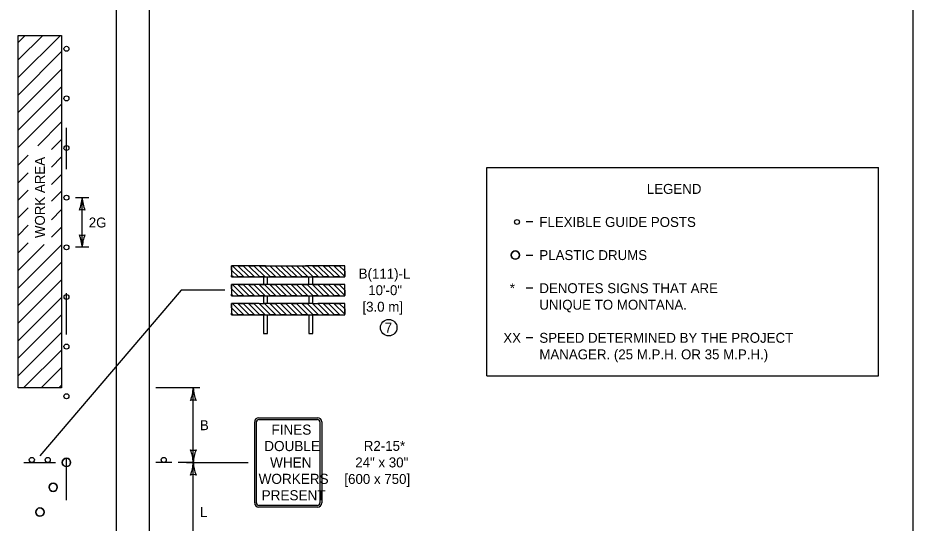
# Model space of a CAD drawing. Extents: x 49991.4 to 50021, y 49987.6 to 50011.4.
# Drawn here: x 50003.21 to 50008.61, y 50003.87 to 50006.92 of the extents above; entities that cross this region are included whole.
import ezdxf

# ---------------------------------------------------------------- set-up
doc = ezdxf.new("R2010")
doc.units = 0
for name, color, linetype in [('Level 1', 7, 'Continuous'), ('Level 2', 7, 'Continuous'), ('Level 3', 7, 'Continuous')]:
    doc.layers.add(name, color=color, linetype=linetype)

msp = doc.modelspace()

# ---------------------------------------------------------------- linework, layer by layer
at = {"layer": 'Level 1'}
for p, q in [((50003.8002, 50009.1708), (50003.8002, 50000.6526)), ((50004.0002, 50009.1708), (50004.0002, 50000.6526)), ((50003.2093, 50006.8139), (50003.4712, 50006.8139)), ((50003.2093, 50004.6829), (50003.2093, 50006.8139)), ((50003.2093, 50006.6656), (50003.3576, 50006.8139)), ((50003.2093, 50006.7716), (50003.2515, 50006.8139)), ((50003.2093, 50006.5595), (50003.4637, 50006.8139)), ((50003.4712, 50006.8139), (50003.4712, 50004.6829)), ((50003.2093, 50006.4534), (50003.4712, 50006.7154)), ((50003.2093, 50006.3474), (50003.4712, 50006.6093)), ((50003.2093, 50006.2413), (50003.4712, 50006.5032)), ((50003.2093, 50006.1352), (50003.4712, 50006.3972)), ((50003.327, 50006.1469), (50003.4712, 50006.2911)), ((50003.5003, 50006.0059), (50003.5003, 50006.2559)), ((50003.4102, 50006.1241), (50003.4712, 50006.185)), ((50003.2093, 50006.0292), (50003.2702, 50006.0901)), ((50003.4102, 50006.018), (50003.4712, 50006.079)), ((50003.2093, 50005.9231), (50003.2702, 50005.9841)), ((50003.4102, 50005.9119), (50003.4712, 50005.9729)), ((50003.2093, 50005.817), (50003.2702, 50005.878)), ((50003.4102, 50005.8119), (50003.4712, 50005.8729)), ((50003.2093, 50005.711), (50003.2702, 50005.7719)), ((50003.4102, 50005.6998), (50003.4712, 50005.7608)), ((50003.2093, 50005.6049), (50003.2702, 50005.6659)), ((50003.4102, 50005.5937), (50003.4712, 50005.6547)), ((50003.2093, 50005.4988), (50003.2702, 50005.5598)), ((50003.2093, 50005.3928), (50003.3665, 50005.55)), ((50003.4102, 50005.4877), (50003.4712, 50005.5486)), ((50003.2093, 50005.2867), (50003.4102, 50005.4877)), ((50003.2093, 50005.1806), (50003.4712, 50005.4426)), ((50004.5397, 50005.3536), (50004.4979, 50005.3954)), ((50004.5397, 50005.3536), (50004.4979, 50005.3954)), ((50004.5719, 50005.3536), (50004.5035, 50005.422)), ((50004.5035, 50005.422), (50004.5719, 50005.3536)), ((50004.6042, 50005.3536), (50004.5358, 50005.422)), ((50004.6042, 50005.3536), (50004.5358, 50005.422)), ((50004.6364, 50005.3536), (50004.568, 50005.422)), ((50004.568, 50005.422), (50004.6364, 50005.3536)), ((50004.6687, 50005.3536), (50004.6003, 50005.422)), ((50004.6687, 50005.3536), (50004.6003, 50005.422)), ((50004.7009, 50005.3536), (50004.6325, 50005.422)), ((50004.6325, 50005.422), (50004.7009, 50005.3536)), ((50004.7332, 50005.3536), (50004.6648, 50005.422)), ((50004.7654, 50005.3536), (50004.697, 50005.422)), ((50004.697, 50005.422), (50004.7369, 50005.422)), ((50004.7174, 50005.422), (50004.9625, 50005.422)), ((50004.7976, 50005.3536), (50004.7292, 50005.422)), ((50004.8298, 50005.3536), (50004.7614, 50005.422)), ((50004.862, 50005.3536), (50004.7936, 50005.422)), ((50004.8942, 50005.3536), (50004.8258, 50005.422)), ((50004.9264, 50005.3536), (50004.858, 50005.422)), ((50004.9586, 50005.3536), (50004.8902, 50005.422)), ((50004.991, 50005.3536), (50004.9226, 50005.422)), ((50004.9767, 50005.422), (50004.9454, 50005.422)), ((50005.0233, 50005.3536), (50004.9549, 50005.422)), ((50005.0556, 50005.3536), (50004.9872, 50005.422)), ((50005.0556, 50005.3536), (50004.9872, 50005.422)), ((50005.0878, 50005.3536), (50005.0194, 50005.422)), ((50005.0194, 50005.422), (50005.0878, 50005.3536)), ((50005.12, 50005.3536), (50005.0516, 50005.422)), ((50005.12, 50005.3536), (50005.0516, 50005.422)), ((50005.1522, 50005.3536), (50005.0838, 50005.422)), ((50005.0838, 50005.422), (50005.1522, 50005.3536)), ((50005.1819, 50005.3562), (50005.1161, 50005.422)), ((50005.1819, 50005.3562), (50005.1161, 50005.422)), ((50005.1819, 50005.3884), (50005.1484, 50005.422)), ((50005.1484, 50005.422), (50005.1819, 50005.3884)), ((50003.2093, 50005.0746), (50003.4712, 50005.3365)), ((50004.5075, 50005.3536), (50004.4979, 50005.3631)), ((50004.4979, 50005.3631), (50004.5075, 50005.3536)), ((50004.7145, 50005.3081), (50004.7145, 50005.3536)), ((50004.9653, 50005.3081), (50004.9653, 50005.3536)), ((50004.5397, 50005.2397), (50004.4979, 50005.2814)), ((50004.5397, 50005.2397), (50004.4979, 50005.2814)), ((50004.5719, 50005.2397), (50004.5035, 50005.3081)), ((50004.5035, 50005.3081), (50004.5719, 50005.2397)), ((50004.6042, 50005.2397), (50004.5358, 50005.3081)), ((50004.6042, 50005.2397), (50004.5358, 50005.3081)), ((50004.6364, 50005.2397), (50004.568, 50005.3081)), ((50004.568, 50005.3081), (50004.6364, 50005.2397)), ((50004.6687, 50005.2397), (50004.6003, 50005.3081)), ((50004.6687, 50005.2397), (50004.6003, 50005.3081)), ((50004.7009, 50005.2397), (50004.6325, 50005.3081)), ((50004.6325, 50005.3081), (50004.7009, 50005.2397)), ((50004.7031, 50005.2697), (50004.6648, 50005.3081)), ((50004.7031, 50005.3019), (50004.697, 50005.3081)), ((50004.7654, 50005.2397), (50004.7031, 50005.3019)), ((50004.7332, 50005.2397), (50004.7031, 50005.2697)), ((50004.7976, 50005.2397), (50004.7292, 50005.3081)), ((50004.8298, 50005.2397), (50004.7614, 50005.3081)), ((50004.8621, 50005.2397), (50004.7937, 50005.3081)), ((50004.8944, 50005.2397), (50004.826, 50005.3081)), ((50004.9266, 50005.2397), (50004.8582, 50005.3081)), ((50004.9588, 50005.2397), (50004.8904, 50005.3081)), ((50004.991, 50005.2397), (50004.9226, 50005.3081)), ((50005.0233, 50005.2397), (50004.9549, 50005.3081)), ((50005.0556, 50005.2397), (50004.9872, 50005.3081)), ((50005.0556, 50005.2397), (50004.9872, 50005.3081)), ((50005.0878, 50005.2397), (50005.0194, 50005.3081)), ((50005.0194, 50005.3081), (50005.0878, 50005.2397)), ((50005.12, 50005.2397), (50005.0516, 50005.3081)), ((50005.12, 50005.2397), (50005.0516, 50005.3081)), ((50005.1522, 50005.2397), (50005.0838, 50005.3081)), ((50005.0838, 50005.3081), (50005.1522, 50005.2397)), ((50005.1819, 50005.2422), (50005.1161, 50005.3081)), ((50005.1819, 50005.2422), (50005.1161, 50005.3081)), ((50005.1819, 50005.2744), (50005.1484, 50005.3081)), ((50005.1484, 50005.3081), (50005.1819, 50005.2744)), ((50003.2093, 50004.9685), (50003.4712, 50005.2304)), ((50003.5003, 50005.0059), (50003.5003, 50005.2559)), ((50004.5075, 50005.2397), (50004.4979, 50005.2492)), ((50004.4979, 50005.2492), (50004.5075, 50005.2397)), ((50004.5397, 50005.1257), (50004.4979, 50005.1674)), ((50004.5397, 50005.1257), (50004.4979, 50005.1674)), ((50004.5719, 50005.1257), (50004.5035, 50005.1941)), ((50004.5035, 50005.1941), (50004.5719, 50005.1257)), ((50004.6042, 50005.1257), (50004.5358, 50005.1941)), ((50004.6042, 50005.1257), (50004.5358, 50005.1941)), ((50004.6364, 50005.1257), (50004.568, 50005.1941)), ((50004.568, 50005.1941), (50004.6364, 50005.1257)), ((50004.6687, 50005.1257), (50004.6003, 50005.1941)), ((50004.6687, 50005.1257), (50004.6003, 50005.1941)), ((50004.7009, 50005.1257), (50004.6325, 50005.1941)), ((50004.6325, 50005.1941), (50004.7009, 50005.1257)), ((50004.7332, 50005.1257), (50004.6648, 50005.1941)), ((50004.7332, 50005.1257), (50004.6648, 50005.1941)), ((50004.7654, 50005.1257), (50004.697, 50005.1941)), ((50004.697, 50005.1941), (50004.7654, 50005.1257)), ((50004.7976, 50005.1257), (50004.7292, 50005.1941)), ((50004.7976, 50005.1257), (50004.7292, 50005.1941)), ((50004.8298, 50005.1257), (50004.7614, 50005.1941)), ((50004.7614, 50005.1941), (50004.8298, 50005.1257)), ((50004.8621, 50005.1257), (50004.7937, 50005.1941)), ((50004.8621, 50005.1257), (50004.7937, 50005.1941)), ((50004.8944, 50005.1257), (50004.826, 50005.1941)), ((50004.826, 50005.1941), (50004.8944, 50005.1257)), ((50004.9266, 50005.1257), (50004.8582, 50005.1941)), ((50004.9266, 50005.1257), (50004.8582, 50005.1941)), ((50004.9588, 50005.1257), (50004.8904, 50005.1941)), ((50004.8904, 50005.1941), (50004.9588, 50005.1257)), ((50004.991, 50005.1257), (50004.9226, 50005.1941)), ((50004.991, 50005.1257), (50004.9226, 50005.1941)), ((50005.0233, 50005.1257), (50004.9549, 50005.1941)), ((50004.9549, 50005.1941), (50005.0233, 50005.1257)), ((50005.0556, 50005.1257), (50004.9872, 50005.1941)), ((50005.0556, 50005.1257), (50004.9872, 50005.1941)), ((50005.0878, 50005.1257), (50005.0194, 50005.1941)), ((50005.0194, 50005.1941), (50005.0878, 50005.1257)), ((50005.12, 50005.1257), (50005.0516, 50005.1941)), ((50005.12, 50005.1257), (50005.0516, 50005.1941)), ((50005.1522, 50005.1257), (50005.0838, 50005.1941)), ((50005.0838, 50005.1941), (50005.1522, 50005.1257)), ((50005.1819, 50005.1282), (50005.1161, 50005.1941)), ((50005.1819, 50005.1282), (50005.1161, 50005.1941)), ((50005.1819, 50005.1605), (50005.1484, 50005.1941)), ((50005.1484, 50005.1941), (50005.1819, 50005.1605)), ((50003.2093, 50004.8624), (50003.4712, 50005.1244)), ((50004.5075, 50005.1257), (50004.4979, 50005.1352)), ((50004.4979, 50005.1352), (50004.5075, 50005.1257)), ((50003.2093, 50004.7564), (50003.4712, 50005.0183)), ((50003.2419, 50004.6829), (50003.4712, 50004.9122)), ((50003.3479, 50004.6829), (50003.4712, 50004.8062)), ((50003.4712, 50004.6829), (50003.2093, 50004.6829)), ((50003.454, 50004.6829), (50003.4712, 50004.7001)), ((50004.6374, 50003.9882), (50004.6374, 50004.4776)), ((50004.6479, 50003.9882), (50004.6479, 50004.4776)), ((50004.6627, 50004.503), (50005.0171, 50004.503)), ((50004.6627, 50004.4924), (50005.0171, 50004.4924)), ((50004.8399, 50004.503), (50004.8399, 50004.503)), ((50005.0319, 50004.4776), (50005.0319, 50003.9882)), ((50005.0424, 50004.4776), (50005.0424, 50003.9882)), ((50003.5003, 50004.0059), (50003.5003, 50004.2559)), ((50003.2433, 50004.2329), (50003.3393, 50004.2329)), ((50003.3393, 50004.2329), (50003.4353, 50004.2329)), ((50004.1362, 50004.2329), (50004.0402, 50004.2329)), ((50005.0171, 50003.9734), (50004.6627, 50003.9734)), ((50005.0171, 50003.9629), (50004.6627, 50003.9629))]:
    msp.add_line(p, q, dxfattribs=at)
msp.add_lwpolyline([(50008.6146, 50011.2628), (50000.3356, 50011.2628), (50000.3356, 50000.0624), (50008.6146, 50000.0624)], close=True, dxfattribs=at)
for points in [[(50004.7031, 50005.422), (50004.4979, 50005.422), (50004.4979, 50005.3536), (50004.7031, 50005.3536)], [(50004.4979, 50005.3954), (50004.4979, 50005.422), (50004.5035, 50005.422)], [(50004.5358, 50005.422), (50004.568, 50005.422)], [(50004.6003, 50005.422), (50004.6325, 50005.422)], [(50004.7654, 50005.3536), (50004.7332, 50005.3536), (50004.6648, 50005.422), (50004.697, 50005.422), (50004.7654, 50005.3536)], [(50004.7031, 50005.3536), (50005.1819, 50005.3536), (50005.1819, 50005.422), (50004.9767, 50005.422)], [(50004.7292, 50005.422), (50004.7369, 50005.422), (50004.7614, 50005.422), (50004.8298, 50005.3536), (50004.7976, 50005.3536), (50004.7292, 50005.422)], [(50004.7936, 50005.422), (50004.8258, 50005.422), (50004.8942, 50005.3536), (50004.862, 50005.3536), (50004.7936, 50005.422)], [(50004.858, 50005.422), (50004.8902, 50005.422), (50004.9586, 50005.3536), (50004.9264, 50005.3536), (50004.858, 50005.422)], [(50004.9226, 50005.422), (50004.9454, 50005.422), (50004.9549, 50005.422), (50005.0233, 50005.3536), (50004.991, 50005.3536), (50004.9226, 50005.422)], [(50004.9872, 50005.422), (50005.0194, 50005.422)], [(50005.0516, 50005.422), (50005.0838, 50005.422)], [(50005.1161, 50005.422), (50005.1484, 50005.422)], [(50005.1819, 50005.3884), (50005.1819, 50005.3562)], [(50004.5075, 50005.3536), (50004.4979, 50005.3536), (50004.4979, 50005.3631)], [(50004.5719, 50005.3536), (50004.5397, 50005.3536)], [(50004.6364, 50005.3536), (50004.6042, 50005.3536)], [(50004.7009, 50005.3536), (50004.6687, 50005.3536)], [(50004.6917, 50005.3536), (50004.6917, 50005.3081)], [(50004.9881, 50005.308), (50004.9881, 50005.3536)], [(50005.0878, 50005.3536), (50005.0556, 50005.3536)], [(50005.1522, 50005.3536), (50005.12, 50005.3536)], [(50004.7031, 50005.3081), (50004.4979, 50005.3081), (50004.4979, 50005.2397), (50005.1819, 50005.2397), (50005.1819, 50005.3081), (50004.7031, 50005.3081)], [(50004.4979, 50005.2814), (50004.4979, 50005.3081), (50004.5035, 50005.3081)], [(50004.5358, 50005.3081), (50004.568, 50005.3081)], [(50004.6003, 50005.3081), (50004.6325, 50005.3081)], [(50004.7654, 50005.2397), (50004.7332, 50005.2397), (50004.7031, 50005.2697), (50004.6648, 50005.3081), (50004.6917, 50005.3081), (50004.697, 50005.3081), (50004.7031, 50005.3019), (50004.7654, 50005.2397)], [(50004.7292, 50005.3081), (50004.7614, 50005.3081), (50004.8298, 50005.2397), (50004.7976, 50005.2397), (50004.7292, 50005.3081)], [(50004.7937, 50005.3081), (50004.826, 50005.3081), (50004.8944, 50005.2397), (50004.8621, 50005.2397), (50004.7937, 50005.3081)], [(50004.8582, 50005.3081), (50004.8904, 50005.3081), (50004.9588, 50005.2397), (50004.9266, 50005.2397), (50004.8582, 50005.3081)], [(50004.9226, 50005.3081), (50004.9549, 50005.3081), (50005.0233, 50005.2397), (50004.991, 50005.2397), (50004.9226, 50005.3081)], [(50004.9872, 50005.3081), (50005.0194, 50005.3081)], [(50005.0516, 50005.3081), (50005.0838, 50005.3081)], [(50005.1161, 50005.3081), (50005.1484, 50005.3081)], [(50005.1819, 50005.2744), (50005.1819, 50005.2422)], [(50004.5075, 50005.2397), (50004.4979, 50005.2397), (50004.4979, 50005.2492)], [(50004.5719, 50005.2397), (50004.5397, 50005.2397)], [(50004.6364, 50005.2397), (50004.6042, 50005.2397)], [(50004.7009, 50005.2397), (50004.6687, 50005.2397)], [(50004.6917, 50005.2397), (50004.6917, 50005.1941)], [(50004.7145, 50005.1941), (50004.7145, 50005.2397)], [(50004.9653, 50005.2397), (50004.9653, 50005.1941)], [(50004.9881, 50005.1941), (50004.9881, 50005.2397)], [(50005.0878, 50005.2397), (50005.0556, 50005.2397)], [(50005.1522, 50005.2397), (50005.12, 50005.2397)], [(50004.4979, 50005.1674), (50004.4979, 50005.1941), (50004.5035, 50005.1941)], [(50004.6648, 50005.1941), (50004.4979, 50005.1941), (50004.4979, 50005.1257), (50005.1819, 50005.1257), (50005.1819, 50005.1941), (50005.0194, 50005.1941)], [(50004.5358, 50005.1941), (50004.568, 50005.1941)], [(50004.6003, 50005.1941), (50004.6325, 50005.1941)], [(50004.6648, 50005.1941), (50004.697, 50005.1941)], [(50004.9872, 50005.1941), (50004.697, 50005.1941)], [(50004.7292, 50005.1941), (50004.7614, 50005.1941)], [(50004.7937, 50005.1941), (50004.826, 50005.1941)], [(50004.8582, 50005.1941), (50004.8904, 50005.1941)], [(50004.9226, 50005.1941), (50004.9549, 50005.1941)], [(50004.9872, 50005.1941), (50005.0194, 50005.1941)], [(50005.0516, 50005.1941), (50005.0838, 50005.1941)], [(50005.1161, 50005.1941), (50005.1484, 50005.1941)], [(50004.5075, 50005.1257), (50004.4979, 50005.1257), (50004.4979, 50005.1352)], [(50004.5719, 50005.1257), (50004.5397, 50005.1257)], [(50004.6364, 50005.1257), (50004.6042, 50005.1257)], [(50004.7009, 50005.1257), (50004.6687, 50005.1257)], [(50004.6917, 50005.1256), (50004.6917, 50005.0116), (50004.7145, 50005.0116), (50004.7145, 50005.1256)], [(50004.7654, 50005.1257), (50004.7332, 50005.1257)], [(50004.8298, 50005.1257), (50004.7976, 50005.1257)], [(50004.8944, 50005.1257), (50004.8621, 50005.1257)], [(50004.9588, 50005.1257), (50004.9266, 50005.1257)], [(50004.9653, 50005.1256), (50004.9653, 50005.0116), (50004.9881, 50005.0116), (50004.9881, 50005.1256)], [(50005.0233, 50005.1257), (50004.991, 50005.1257)], [(50005.0878, 50005.1257), (50005.0556, 50005.1257)], [(50005.1522, 50005.1257), (50005.12, 50005.1257)], [(50005.1819, 50005.1605), (50005.1819, 50005.1282)]]:
    msp.add_lwpolyline(points, dxfattribs=at)
for centre, radius in [((50003.5003, 50006.7329), 0.015), ((50003.5003, 50006.4329), 0.015), ((50003.5003, 50006.1329), 0.015), ((50003.5003, 50005.8329), 0.015), ((50006.222, 50005.686), 0.015), ((50003.5003, 50005.5329), 0.015), ((50006.212, 50005.486), 0.025), ((50003.5003, 50005.2329), 0.015), ((50003.5003, 50004.9329), 0.015), ((50003.5003, 50004.6329), 0.015), ((50003.2913, 50004.2481), 0.0152), ((50003.3873, 50004.2481), 0.0152), ((50003.5003, 50004.2329), 0.025), ((50004.0881, 50004.2481), 0.0152), ((50003.4203, 50004.0829), 0.025), ((50003.3403, 50003.9329), 0.025)]:
    msp.add_circle(centre, radius, dxfattribs=at)
for centre, radius, start, end in [((50006.212, 50005.486), 0.025, 360, 180), ((50006.212, 50005.486), 0.025, 180, 0), ((50004.6627, 50004.4776), 0.0253, 90, 180), ((50004.6627, 50004.4776), 0.0148, 90, 180), ((50005.0171, 50004.4776), 0.0253, 0, 90), ((50005.0171, 50004.4776), 0.0148, 0, 90), ((50003.5003, 50004.2329), 0.025, 0, 180), ((50003.5003, 50004.2329), 0.025, 180, 0), ((50003.4203, 50004.0829), 0.025, 0, 180), ((50003.4203, 50004.0829), 0.025, 180, 0), ((50004.6627, 50003.9882), 0.0253, 180, 270), ((50004.6627, 50003.9882), 0.0148, 180, 270), ((50005.0171, 50003.9882), 0.0148, 270, 360), ((50005.0171, 50003.9882), 0.0253, 270, 360), ((50003.3403, 50003.9329), 0.025, 0, 180), ((50003.3403, 50003.9329), 0.025, 180, 0)]:
    msp.add_arc(centre, radius, start, end, dxfattribs=at)
at = {"layer": 'Level 2'}
for p, q in [((50006.0392, 50004.756), (50006.0392, 50006.016)), ((50008.4059, 50004.756), (50008.4059, 50006.016)), ((50006.317, 50005.686), (50006.277, 50005.686)), ((50006.277, 50005.486), (50006.317, 50005.486)), ((50006.317, 50005.286), (50006.277, 50005.286)), ((50006.317, 50004.986), (50006.277, 50004.986)), ((50006.0392, 50004.756), (50008.4059, 50004.756))]:
    msp.add_line(p, q, dxfattribs=at)
msp.add_lwpolyline([(50006.0392, 50006.016), (50008.4059, 50006.016)], dxfattribs=at)
msp.add_circle((50005.447, 50005.0475), 0.0501, dxfattribs=at)
at = {"layer": 'Level 3'}
for p, q in [((50003.6353, 50005.8329), (50003.5553, 50005.8329)), ((50003.5953, 50005.5329), (50003.5953, 50005.8329)), ((50003.6353, 50005.5329), (50003.5553, 50005.5329)), ((50004.1937, 50005.2739), (50003.3393, 50004.2729)), ((50004.4579, 50005.2739), (50004.1937, 50005.2739)), ((50004.3065, 50004.6829), (50004.0402, 50004.6829)), ((50004.2665, 50004.2329), (50004.2665, 50004.6829)), ((50004.2665, 50004.2329), (50004.1762, 50004.2329)), ((50004.2251, 50004.2329), (50004.5974, 50004.2329)), ((50004.2665, 50004.2329), (50004.3665, 50004.2329)), ((50004.2665, 50003.6329), (50004.2665, 50004.2329))]:
    msp.add_line(p, q, dxfattribs=at)
for centre, radius, start, end in [((50003.3732, 50005.8421), 0.2223, 337.456, 357.6395), ((50003.828, 50005.8444), 0.233, 182.8273, 202.0772), ((50003.5953, 50005.7047), 0.0548, 72.1388, 107.8612), ((50003.5953, 50005.6611), 0.0548, 252.1388, 287.8612), ((50003.3626, 50005.5214), 0.233, 2.8273, 22.0772), ((50003.8175, 50005.5238), 0.2223, 157.456, 177.6395), ((50004.0444, 50004.6921), 0.2223, 337.456, 357.6395), ((50004.4992, 50004.6944), 0.233, 182.8273, 202.0772), ((50004.2665, 50004.5547), 0.0548, 72.1388, 107.8612), ((50004.2665, 50004.3611), 0.0548, 252.1388, 287.8612), ((50004.0338, 50004.2214), 0.233, 2.8273, 22.0772), ((50004.4886, 50004.2238), 0.2223, 157.456, 177.6395), ((50004.0444, 50004.2421), 0.2223, 337.456, 357.6395), ((50004.4992, 50004.2444), 0.233, 182.8273, 202.0772), ((50004.2665, 50004.1047), 0.0548, 72.1388, 107.8612)]:
    msp.add_arc(centre, radius, start, end, dxfattribs=at)

# ---------------------------------------------------------------- texts
at = {"layer": 'Level 1'}
for s, p in [('FINES', (50004.7387, 50004.4006)), ('DOUBLE', (50004.6953, 50004.3015)), ('WHEN', (50004.7307, 50004.2023)), ('WORKERS', (50004.6613, 50004.1032)), ('PRESENT', (50004.6794, 50004.004))]:
    msp.add_text(s, height=0.06118, dxfattribs=at).set_placement(p)
at = {"layer": 'Level 2'}
msp.add_text('WORK AREA', height=0.06, rotation=90, dxfattribs=at).set_placement((50003.3702, 50005.5889))
for s, p in [('LEGEND', (50007.0062, 50005.856)), ('2G', (50003.6353, 50005.6529)), ('FLEXIBLE GUIDE POSTS', (50006.357, 50005.656)), ('PLASTIC DRUMS', (50006.357, 50005.456)), ('B(111)-L', (50005.2657, 50005.3439)), ('10\'-0"', (50005.3235, 50005.2439)), ('*', (50006.1784, 50005.256)), ('DENOTES SIGNS THAT ARE', (50006.357, 50005.256)), ('UNIQUE TO MONTANA.', (50006.357, 50005.156)), ('[3.0 m]', (50005.2883, 50005.1439)), ('7', (50005.4232, 50005.0175)), ('XX', (50006.1392, 50004.956)), ('SPEED DETERMINED BY THE PROJECT ', (50006.357, 50004.956)), ('MANAGER. (25 M.P.H. OR 35 M.P.H.)', (50006.357, 50004.856)), ('B', (50004.3065, 50004.4279)), ('R2-15*', (50005.2966, 50004.3029)), ('24" x 30"', (50005.2451, 50004.2029)), ('[600 x 750]', (50005.1795, 50004.1029)), ('L', (50004.3065, 50003.9029))]:
    msp.add_text(s, height=0.06, dxfattribs=at).set_placement(p)

doc.saveas('drawing.dxf')
